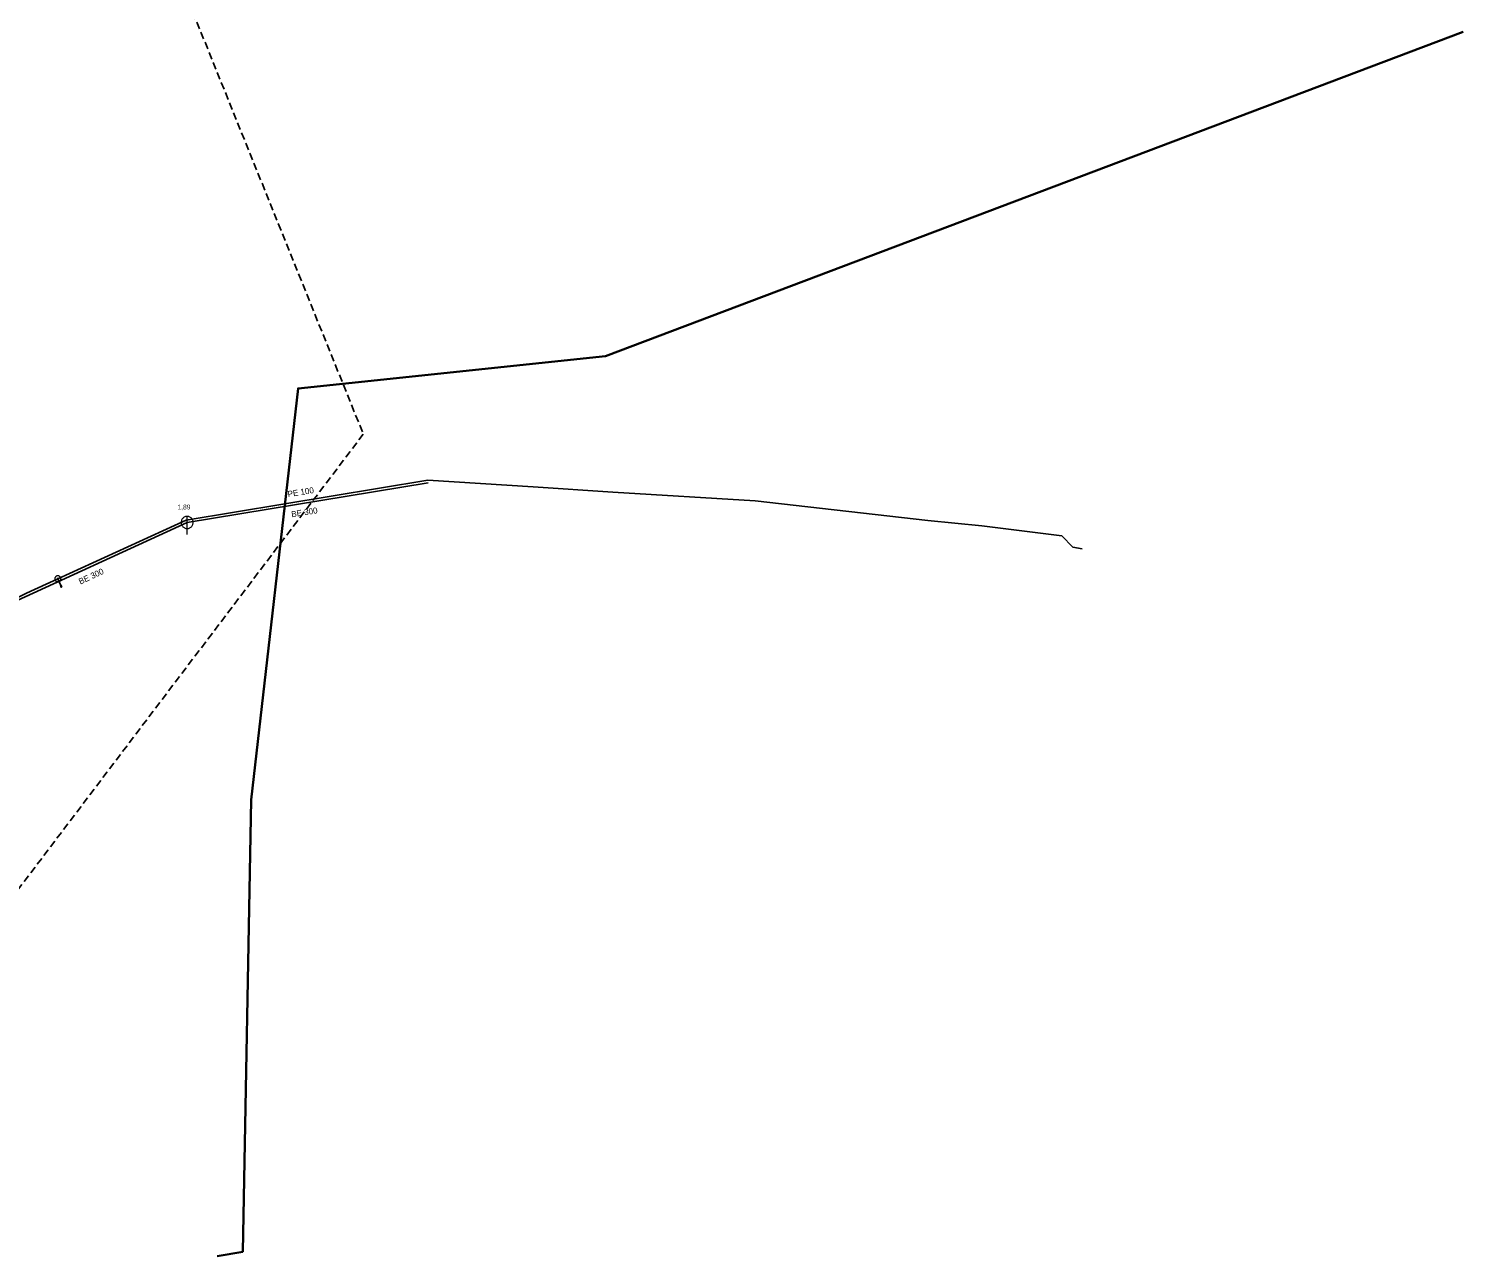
# Model space of a CAD drawing. Extents: x -682839 to -682312, y -994645 to -993949.
# Drawn here: x -682550 to -682312.5, y -994614.2 to -994410.8 of the extents above; entities that cross this region are included whole.
import ezdxf

# ---------------------------------------------------------------- set-up
doc = ezdxf.new("R2010")
doc.units = 0
doc.header["$LTSCALE"] = 0.4
doc.linetypes.add('MEDIUM_DASHED', pattern=[4.5, 3, -1.5])
doc.layers.add('1', color=7, linetype='Continuous')
for name, color, linetype, lineweight in [('14', 7, 'Continuous', 25), ('17', 7, 'Continuous', 25), ('22', 7, 'Continuous', 13), ('34', 7, 'Continuous', 13), ('47', 7, 'Continuous', 13), ('63', 7, 'MEDIUM_DASHED', 25), ('9', 7, 'Continuous', 13)]:
    doc.layers.add(name, color=color, linetype=linetype, lineweight=lineweight)

msp = doc.modelspace()

# ---------------------------------------------------------------- linework, layer by layer
at = {"layer": '14'}
for p, q in [((-682483.87, -994486.01), (-682523.789, -994492.6)), ((-682523.789, -994492.6), (-682555.35, -994507.1))]:
    msp.add_line(p, q, dxfattribs=at)
at = {"layer": '14', "lineweight": 13}
msp.add_line((-682545.21, -994501.938), (-682545.056, -994502.276), dxfattribs=at)
at = {"layer": '17'}
msp.add_line((-682545.056, -994502.276), (-682544.64, -994503.19), dxfattribs=at)
at = {"layer": '17', "lineweight": 35}
msp.add_lwpolyline([(-682312.469, -994411.329), (-682454.524, -994465.059), (-682505.421, -994470.392), (-682513.206, -994538.57), (-682514.572, -994613.423), (-682518.839, -994614.18)], dxfattribs=at)
at = {"layer": '17'}
for points in [[(-682375.579, -994496.969), (-682377.14, -994496.68), (-682378.94, -994494.82), (-682392.199, -994493.18), (-682401.14, -994492.28), (-682429.719, -994489.03), (-682453.309, -994487.579), (-682466.467, -994486.72), (-682483.93, -994485.579), (-682523.98, -994492.21), (-682545.21, -994501.938)], [(-682545.21, -994501.938), (-682550.42, -994504.32), (-682558.315, -994508.18), (-682561.019, -994509.629), (-682567.699, -994513.21), (-682611.829, -994539.23), (-682623.82, -994545.199), (-682650.23, -994552.17), (-682658.579, -994554.37), (-682723.739, -994569.28), (-682738.277, -994572.726), (-682751.844, -994575.85), (-682782.859, -994582.98), (-682788.5, -994584.28), (-682800.07, -994586.93), (-682812.989, -994588.3), (-682831.809, -994590.289), (-682831.911, -994590.301), (-682838.501, -994590.936)]]:
    msp.add_lwpolyline(points, dxfattribs=at)
at = {"layer": '22'}
msp.add_line((-682523.789, -994494.6), (-682523.788, -994491.6), dxfattribs=at)
msp.add_lwpolyline([(-682522.789, -994492.6), (-682522.794, -994492.491), (-682522.812, -994492.383), (-682522.842, -994492.277), (-682522.882, -994492.176), (-682522.934, -994492.079), (-682522.996, -994491.989), (-682523.068, -994491.906), (-682523.148, -994491.832), (-682523.236, -994491.766), (-682523.33, -994491.711), (-682523.43, -994491.666), (-682523.535, -994491.633), (-682523.642, -994491.611), (-682523.751, -994491.601), (-682523.861, -994491.603), (-682523.969, -994491.617), (-682524.076, -994491.642), (-682524.179, -994491.679), (-682524.277, -994491.728), (-682524.369, -994491.786), (-682524.455, -994491.855), (-682524.532, -994491.932), (-682524.601, -994492.018), (-682524.66, -994492.11), (-682524.708, -994492.208), (-682524.745, -994492.311), (-682524.771, -994492.418), (-682524.785, -994492.526), (-682524.788, -994492.636), (-682524.778, -994492.745), (-682524.757, -994492.852), (-682524.723, -994492.956), (-682524.679, -994493.056), (-682524.624, -994493.151), (-682524.558, -994493.239), (-682524.484, -994493.319), (-682524.401, -994493.391), (-682524.311, -994493.453), (-682524.215, -994493.505), (-682524.113, -994493.546), (-682524.008, -994493.576), (-682523.9, -994493.594), (-682523.79, -994493.6), (-682523.681, -994493.594), (-682523.573, -994493.576), (-682523.468, -994493.547), (-682523.366, -994493.506), (-682523.269, -994493.454), (-682523.179, -994493.392), (-682523.096, -994493.321), (-682523.021, -994493.241), (-682522.956, -994493.153), (-682522.9, -994493.059), (-682522.856, -994492.959), (-682522.822, -994492.855), (-682522.8, -994492.747), (-682522.79, -994492.638)], close=True, dxfattribs=at)
at = {"layer": '34'}
msp.add_line((-682544.601, -994502.067), (-682545.51, -994502.483), dxfattribs=at)
at = {"layer": '47'}
for points in [[(-682544.71, -994501.938), (-682544.713, -994501.886), (-682544.721, -994501.833), (-682544.735, -994501.784), (-682544.752, -994501.735), (-682544.777, -994501.688), (-682544.806, -994501.644), (-682544.838, -994501.603), (-682544.875, -994501.566), (-682544.916, -994501.534), (-682544.96, -994501.505), (-682545.007, -994501.48), (-682545.056, -994501.463), (-682545.105, -994501.449), (-682545.157, -994501.441), (-682545.21, -994501.438), (-682545.262, -994501.441), (-682545.314, -994501.449), (-682545.365, -994501.463), (-682545.413, -994501.48), (-682545.46, -994501.505), (-682545.504, -994501.534), (-682545.544, -994501.566), (-682545.581, -994501.603), (-682545.615, -994501.644), (-682545.642, -994501.688), (-682545.667, -994501.735), (-682545.686, -994501.784), (-682545.698, -994501.833), (-682545.706, -994501.886), (-682545.71, -994501.938), (-682545.706, -994501.99), (-682545.698, -994502.042), (-682545.686, -994502.093), (-682545.667, -994502.141), (-682545.642, -994502.188), (-682545.615, -994502.232), (-682545.581, -994502.272), (-682545.544, -994502.309), (-682545.504, -994502.343), (-682545.46, -994502.37), (-682545.413, -994502.395), (-682545.365, -994502.414), (-682545.314, -994502.426), (-682545.262, -994502.434), (-682545.21, -994502.438), (-682545.157, -994502.434), (-682545.105, -994502.426), (-682545.056, -994502.414), (-682545.007, -994502.395), (-682544.96, -994502.37), (-682544.916, -994502.343), (-682544.875, -994502.309), (-682544.838, -994502.272), (-682544.806, -994502.232), (-682544.777, -994502.188), (-682544.752, -994502.141), (-682544.735, -994502.093), (-682544.721, -994502.042), (-682544.713, -994501.99)], [(-682545.127, -994501.938), (-682545.127, -994501.929), (-682545.13, -994501.921), (-682545.132, -994501.913), (-682545.135, -994501.904), (-682545.139, -994501.897), (-682545.144, -994501.89), (-682545.149, -994501.882), (-682545.154, -994501.877), (-682545.162, -994501.872), (-682545.169, -994501.867), (-682545.176, -994501.863), (-682545.184, -994501.86), (-682545.193, -994501.858), (-682545.201, -994501.855), (-682545.21, -994501.855), (-682545.218, -994501.855), (-682545.227, -994501.858), (-682545.235, -994501.86), (-682545.243, -994501.863), (-682545.25, -994501.867), (-682545.257, -994501.872), (-682545.265, -994501.877), (-682545.271, -994501.882), (-682545.277, -994501.89), (-682545.281, -994501.897), (-682545.284, -994501.904), (-682545.288, -994501.913), (-682545.289, -994501.921), (-682545.292, -994501.929), (-682545.292, -994501.938), (-682545.292, -994501.946), (-682545.289, -994501.955), (-682545.288, -994501.963), (-682545.284, -994501.971), (-682545.281, -994501.978), (-682545.277, -994501.985), (-682545.271, -994501.993), (-682545.265, -994501.999), (-682545.257, -994502.005), (-682545.25, -994502.009), (-682545.243, -994502.012), (-682545.235, -994502.016), (-682545.227, -994502.017), (-682545.218, -994502.02), (-682545.21, -994502.02), (-682545.201, -994502.02), (-682545.193, -994502.017), (-682545.184, -994502.016), (-682545.176, -994502.012), (-682545.169, -994502.009), (-682545.162, -994502.005), (-682545.154, -994501.999), (-682545.149, -994501.993), (-682545.144, -994501.985), (-682545.139, -994501.978), (-682545.135, -994501.971), (-682545.132, -994501.963), (-682545.13, -994501.955), (-682545.127, -994501.946)]]:
    msp.add_lwpolyline(points, close=True, dxfattribs=at)
at = {"layer": '63'}
msp.add_lwpolyline([(-682494.62, -994477.955), (-682564.4, -994570.065), (-682564.4, -994570.065), (-682684.423, -994544.944), (-682684.423, -994544.944), (-682751.412, -994042.525), (-682751.412, -994042.525), (-682670.466, -994042.525), (-682670.466, -994042.525)], close=True, dxfattribs=at)
at = {"layer": '9'}
for points in [[(-682544.766, -994503.19), (-682544.766, -994503.203), (-682544.764, -994503.216), (-682544.761, -994503.229), (-682544.756, -994503.241), (-682544.75, -994503.253), (-682544.743, -994503.264), (-682544.735, -994503.274), (-682544.725, -994503.284), (-682544.715, -994503.292), (-682544.704, -994503.299), (-682544.692, -994503.305), (-682544.68, -994503.31), (-682544.667, -994503.313), (-682544.654, -994503.315), (-682544.641, -994503.317), (-682544.628, -994503.316), (-682544.615, -994503.314), (-682544.602, -994503.311), (-682544.59, -994503.306), (-682544.578, -994503.3), (-682544.567, -994503.293), (-682544.557, -994503.285), (-682544.547, -994503.275), (-682544.539, -994503.265), (-682544.532, -994503.254), (-682544.526, -994503.242), (-682544.521, -994503.23), (-682544.518, -994503.217), (-682544.516, -994503.204), (-682544.514, -994503.191), (-682544.515, -994503.178), (-682544.517, -994503.165), (-682544.52, -994503.152), (-682544.525, -994503.14), (-682544.531, -994503.128), (-682544.538, -994503.117), (-682544.546, -994503.107), (-682544.556, -994503.097), (-682544.566, -994503.089), (-682544.577, -994503.082), (-682544.589, -994503.076), (-682544.601, -994503.071), (-682544.614, -994503.068), (-682544.627, -994503.066), (-682544.64, -994503.065), (-682544.653, -994503.065), (-682544.666, -994503.067), (-682544.679, -994503.07), (-682544.691, -994503.075), (-682544.703, -994503.081), (-682544.714, -994503.088), (-682544.724, -994503.096), (-682544.734, -994503.106), (-682544.742, -994503.116), (-682544.749, -994503.127), (-682544.755, -994503.139), (-682544.76, -994503.151), (-682544.763, -994503.164), (-682544.765, -994503.177)], [(-682544.746, -994503.19), (-682544.747, -994503.201), (-682544.745, -994503.212), (-682544.742, -994503.223), (-682544.738, -994503.233), (-682544.733, -994503.243), (-682544.727, -994503.252), (-682544.72, -994503.261), (-682544.712, -994503.269), (-682544.703, -994503.276), (-682544.694, -994503.282), (-682544.684, -994503.287), (-682544.674, -994503.291), (-682544.663, -994503.294), (-682544.652, -994503.297), (-682544.641, -994503.297), (-682544.63, -994503.297), (-682544.619, -994503.295), (-682544.608, -994503.292), (-682544.598, -994503.288), (-682544.588, -994503.283), (-682544.579, -994503.277), (-682544.57, -994503.27), (-682544.562, -994503.262), (-682544.555, -994503.253), (-682544.549, -994503.244), (-682544.544, -994503.234), (-682544.54, -994503.224), (-682544.537, -994503.213), (-682544.535, -994503.202), (-682544.534, -994503.191), (-682544.534, -994503.18), (-682544.536, -994503.169), (-682544.539, -994503.158), (-682544.543, -994503.148), (-682544.548, -994503.138), (-682544.554, -994503.129), (-682544.561, -994503.12), (-682544.569, -994503.112), (-682544.578, -994503.105), (-682544.587, -994503.099), (-682544.597, -994503.094), (-682544.607, -994503.09), (-682544.618, -994503.087), (-682544.629, -994503.085), (-682544.64, -994503.085), (-682544.651, -994503.084), (-682544.662, -994503.086), (-682544.673, -994503.089), (-682544.683, -994503.093), (-682544.693, -994503.098), (-682544.702, -994503.104), (-682544.711, -994503.111), (-682544.719, -994503.119), (-682544.726, -994503.128), (-682544.732, -994503.137), (-682544.737, -994503.147), (-682544.741, -994503.157), (-682544.744, -994503.168), (-682544.746, -994503.179)], [(-682544.727, -994503.19), (-682544.727, -994503.199), (-682544.726, -994503.208), (-682544.723, -994503.217), (-682544.72, -994503.225), (-682544.716, -994503.233), (-682544.711, -994503.241), (-682544.705, -994503.248), (-682544.699, -994503.254), (-682544.692, -994503.26), (-682544.684, -994503.265), (-682544.676, -994503.269), (-682544.668, -994503.272), (-682544.659, -994503.275), (-682544.65, -994503.276), (-682544.641, -994503.278), (-682544.632, -994503.277), (-682544.623, -994503.276), (-682544.614, -994503.273), (-682544.606, -994503.27), (-682544.598, -994503.266), (-682544.59, -994503.261), (-682544.583, -994503.255), (-682544.577, -994503.249), (-682544.571, -994503.242), (-682544.566, -994503.234), (-682544.562, -994503.226), (-682544.559, -994503.218), (-682544.556, -994503.209), (-682544.555, -994503.2), (-682544.553, -994503.191), (-682544.554, -994503.182), (-682544.555, -994503.173), (-682544.558, -994503.164), (-682544.561, -994503.156), (-682544.565, -994503.148), (-682544.57, -994503.14), (-682544.576, -994503.133), (-682544.582, -994503.127), (-682544.589, -994503.121), (-682544.597, -994503.116), (-682544.605, -994503.112), (-682544.613, -994503.109), (-682544.622, -994503.106), (-682544.631, -994503.105), (-682544.64, -994503.104), (-682544.649, -994503.104), (-682544.658, -994503.105), (-682544.667, -994503.108), (-682544.675, -994503.111), (-682544.683, -994503.115), (-682544.691, -994503.12), (-682544.698, -994503.126), (-682544.704, -994503.132), (-682544.71, -994503.139), (-682544.715, -994503.147), (-682544.719, -994503.155), (-682544.722, -994503.163), (-682544.725, -994503.172), (-682544.726, -994503.181)], [(-682544.707, -994503.19), (-682544.707, -994503.197), (-682544.706, -994503.204), (-682544.705, -994503.211), (-682544.702, -994503.217), (-682544.699, -994503.223), (-682544.695, -994503.229), (-682544.691, -994503.235), (-682544.686, -994503.24), (-682544.68, -994503.244), (-682544.674, -994503.248), (-682544.668, -994503.251), (-682544.662, -994503.254), (-682544.655, -994503.255), (-682544.648, -994503.258), (-682544.641, -994503.258), (-682544.634, -994503.258), (-682544.627, -994503.256), (-682544.62, -994503.255), (-682544.614, -994503.252), (-682544.607, -994503.249), (-682544.602, -994503.245), (-682544.596, -994503.241), (-682544.591, -994503.236), (-682544.587, -994503.23), (-682544.583, -994503.224), (-682544.58, -994503.218), (-682544.577, -994503.212), (-682544.575, -994503.205), (-682544.574, -994503.198), (-682544.573, -994503.191), (-682544.573, -994503.184), (-682544.574, -994503.177), (-682544.576, -994503.17), (-682544.579, -994503.164), (-682544.582, -994503.157), (-682544.586, -994503.152), (-682544.59, -994503.146), (-682544.595, -994503.141), (-682544.601, -994503.137), (-682544.606, -994503.133), (-682544.613, -994503.13), (-682544.619, -994503.127), (-682544.626, -994503.125), (-682544.633, -994503.124), (-682544.64, -994503.124), (-682544.647, -994503.124), (-682544.654, -994503.124), (-682544.661, -994503.126), (-682544.667, -994503.129), (-682544.673, -994503.132), (-682544.679, -994503.136), (-682544.685, -994503.14), (-682544.69, -994503.145), (-682544.694, -994503.151), (-682544.698, -994503.156), (-682544.701, -994503.163), (-682544.704, -994503.169), (-682544.705, -994503.176), (-682544.707, -994503.183)], [(-682544.687, -994503.19), (-682544.687, -994503.195), (-682544.687, -994503.2), (-682544.686, -994503.205), (-682544.684, -994503.209), (-682544.682, -994503.214), (-682544.679, -994503.218), (-682544.676, -994503.221), (-682544.672, -994503.225), (-682544.669, -994503.228), (-682544.665, -994503.231), (-682544.66, -994503.233), (-682544.656, -994503.235), (-682544.651, -994503.236), (-682544.646, -994503.238), (-682544.641, -994503.238), (-682544.636, -994503.238), (-682544.631, -994503.237), (-682544.626, -994503.236), (-682544.622, -994503.234), (-682544.617, -994503.232), (-682544.613, -994503.229), (-682544.609, -994503.226), (-682544.606, -994503.222), (-682544.603, -994503.219), (-682544.6, -994503.215), (-682544.598, -994503.21), (-682544.596, -994503.206), (-682544.595, -994503.201), (-682544.594, -994503.196), (-682544.593, -994503.191), (-682544.593, -994503.186), (-682544.594, -994503.181), (-682544.595, -994503.176), (-682544.597, -994503.172), (-682544.599, -994503.167), (-682544.602, -994503.163), (-682544.605, -994503.159), (-682544.608, -994503.156), (-682544.612, -994503.153), (-682544.616, -994503.15), (-682544.621, -994503.148), (-682544.625, -994503.146), (-682544.63, -994503.145), (-682544.635, -994503.144), (-682544.64, -994503.144), (-682544.645, -994503.144), (-682544.65, -994503.145), (-682544.655, -994503.145), (-682544.659, -994503.147), (-682544.664, -994503.149), (-682544.668, -994503.152), (-682544.671, -994503.155), (-682544.675, -994503.158), (-682544.678, -994503.162), (-682544.681, -994503.166), (-682544.683, -994503.171), (-682544.685, -994503.175), (-682544.686, -994503.18), (-682544.687, -994503.185)], [(-682544.667, -994503.19), (-682544.667, -994503.193), (-682544.668, -994503.196), (-682544.667, -994503.198), (-682544.666, -994503.201), (-682544.665, -994503.204), (-682544.663, -994503.206), (-682544.661, -994503.208), (-682544.659, -994503.21), (-682544.657, -994503.212), (-682544.655, -994503.214), (-682544.652, -994503.216), (-682544.649, -994503.217), (-682544.647, -994503.217), (-682544.644, -994503.218), (-682544.641, -994503.218), (-682544.638, -994503.218), (-682544.635, -994503.218), (-682544.632, -994503.217), (-682544.63, -994503.216), (-682544.627, -994503.215), (-682544.625, -994503.213), (-682544.622, -994503.211), (-682544.62, -994503.209), (-682544.619, -994503.207), (-682544.617, -994503.205), (-682544.616, -994503.202), (-682544.614, -994503.199), (-682544.614, -994503.197), (-682544.613, -994503.194), (-682544.612, -994503.191), (-682544.613, -994503.188), (-682544.613, -994503.185), (-682544.614, -994503.182), (-682544.615, -994503.18), (-682544.616, -994503.177), (-682544.618, -994503.175), (-682544.619, -994503.172), (-682544.621, -994503.17), (-682544.624, -994503.169), (-682544.626, -994503.167), (-682544.629, -994503.166), (-682544.631, -994503.165), (-682544.634, -994503.164), (-682544.637, -994503.164), (-682544.64, -994503.163), (-682544.643, -994503.164), (-682544.646, -994503.163), (-682544.648, -994503.165), (-682544.651, -994503.165), (-682544.654, -994503.166), (-682544.656, -994503.168), (-682544.658, -994503.169), (-682544.66, -994503.171), (-682544.662, -994503.174), (-682544.664, -994503.176), (-682544.665, -994503.179), (-682544.666, -994503.181), (-682544.667, -994503.184), (-682544.667, -994503.187)], [(-682544.648, -994503.19), (-682544.648, -994503.192), (-682544.648, -994503.192), (-682544.647, -994503.192), (-682544.647, -994503.194), (-682544.648, -994503.195), (-682544.646, -994503.195), (-682544.646, -994503.195), (-682544.646, -994503.197), (-682544.646, -994503.197), (-682544.645, -994503.198), (-682544.643, -994503.198), (-682544.643, -994503.198), (-682544.643, -994503.199), (-682544.641, -994503.199), (-682544.641, -994503.199), (-682544.64, -994503.199), (-682544.639, -994503.199), (-682544.639, -994503.198), (-682544.638, -994503.198), (-682544.636, -994503.198), (-682544.636, -994503.197), (-682544.636, -994503.197), (-682544.635, -994503.196), (-682544.635, -994503.196), (-682544.633, -994503.195), (-682544.633, -994503.194), (-682544.632, -994503.193), (-682544.632, -994503.193), (-682544.632, -994503.192), (-682544.632, -994503.191), (-682544.632, -994503.19), (-682544.632, -994503.189), (-682544.632, -994503.189), (-682544.633, -994503.188), (-682544.633, -994503.187), (-682544.634, -994503.186), (-682544.634, -994503.186), (-682544.635, -994503.185), (-682544.635, -994503.185), (-682544.636, -994503.184), (-682544.637, -994503.184), (-682544.638, -994503.183), (-682544.638, -994503.183), (-682544.639, -994503.183), (-682544.64, -994503.183), (-682544.641, -994503.183), (-682544.642, -994503.183), (-682544.642, -994503.183), (-682544.643, -994503.184), (-682544.644, -994503.183), (-682544.645, -994503.185), (-682544.645, -994503.185), (-682544.646, -994503.185), (-682544.646, -994503.185), (-682544.647, -994503.187), (-682544.647, -994503.188), (-682544.647, -994503.189), (-682544.648, -994503.189), (-682544.648, -994503.19)]]:
    msp.add_lwpolyline(points, close=True, dxfattribs=at)

# ---------------------------------------------------------------- texts
at = {"layer": '1'}
for s, rotation, p in [('PE 100', 9, (-682507.075, -994488.412)), ('BE 300', 9, (-682506.466, -994491.751)), ('BE 300', 25, (-682541.466, -994502.905))]:
    msp.add_text(s, height=1, rotation=rotation, dxfattribs=at).set_placement(p)
msp.add_text('1,89', height=0.8, dxfattribs=at).set_placement((-682525.389, -994490.447))

doc.saveas('drawing.dxf')
